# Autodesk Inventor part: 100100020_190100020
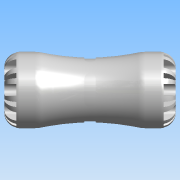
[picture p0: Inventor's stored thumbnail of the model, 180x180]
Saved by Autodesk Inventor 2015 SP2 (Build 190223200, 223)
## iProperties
Created: 2016-12
Part Number: 100100020_190100020
Material: PVC-Piping
Description: PLASSON COUPLER 20X20 SERIES 1
Document SubType Name: Modeling
Designer: KIM
Mass: 95.2094 g
Surface Area: 200.83 cm^2
Volume: 68.0067 cm^3
Density: 1.4 g/cm^3
Appearance: Smooth - White
ILogicFactory: False
Author: KIM
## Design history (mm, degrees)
derived "1001.ipt"
feature "Solid1::1001.ipt"
tag "TaggingFeature1"
body "Solid1"
other parameters: "d2" = 45, "d4" = 1.66667, "d11" = 6.4, "d13" = 6.4, "d14" = 0, "d16" = 360 deg, "d18" = 8 deg, "d19" = 0.4, "d20" = 8 deg, "d21" = 0.4, "d23" = 0, "d25" = 360 deg, "d27" = 16.4, "d28" = 6, "d29" = 6, "d30" = 6, "d31" = 0, "d33" = 0, "d37" = 18.4, "d38" = 0.41, "d43" = 2.5, "d45" = 18.4, "d46" = 34.85, "d47" = 41, "d48" = 92, "d50" = 360 deg, "d54" = 0.513, "E_" = 41, "H_" = 92, "l_" = 45, "d12" = 25, "d42" = 41, "d52" = 8
